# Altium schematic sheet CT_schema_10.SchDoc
size 277 x 170 mm
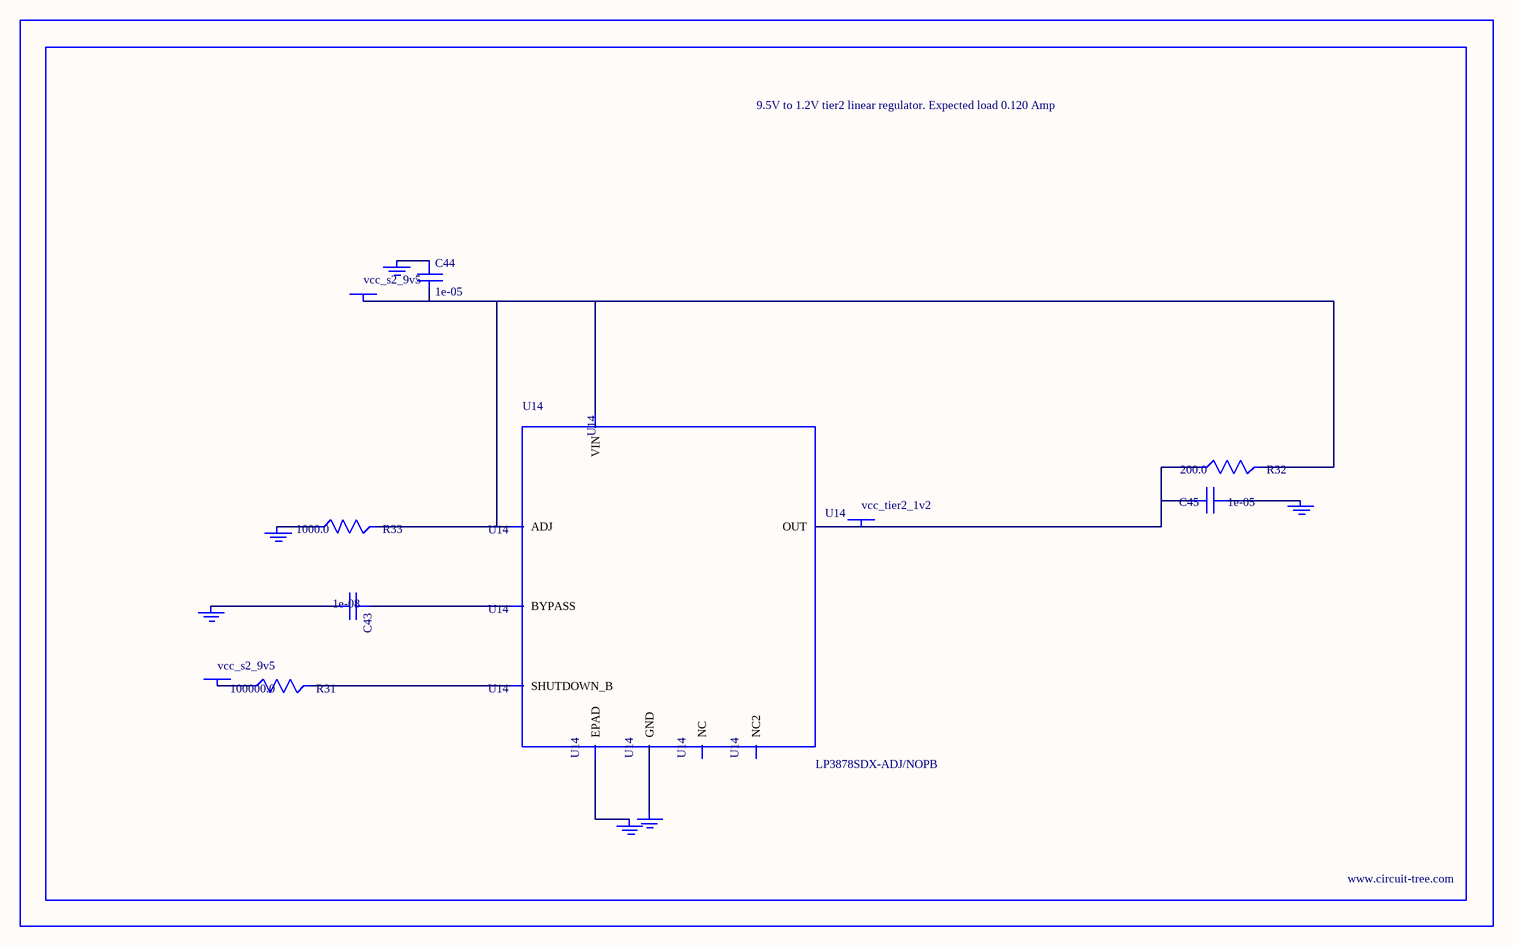
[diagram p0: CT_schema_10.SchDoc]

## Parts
BORDER9  (no value)
C43  1e-08  [C0402]
C44  1e-05  [C1206]
C45  1e-05  [C0805]
GND_INSTANCE_9_0  (no value)
GND_INSTANCE_9_1  (no value)
GND_INSTANCE_9_2  (no value)
GND_INSTANCE_9_3  (no value)
GND_INSTANCE_9_4  (no value)
GND_INSTANCE_9_5  (no value)
POWER_INSTANCE_9_0  vcc_s2_9v5
POWER_INSTANCE_9_1  vcc_s2_9v5
POWER_INSTANCE_9_2  vcc_tier2_1v2
R31  100000.0  [R0603]
R32  200.0  [R0603]
R33  1000.0  [R0603]
U14  LP3878SDX-ADJ/NOPB  [WSON-8]

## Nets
NetC43_1: C43.1 U14.1(BYPASS)
NetC43_2: C43.2 GND_INSTANCE_9_0.0(GND)
NetC44_1: C44.1 GND_INSTANCE_9_1.0(GND)
NetC44_2: C44.2 POWER_INSTANCE_9_0.0(PWR) R32.2 R33.2 U14.4(VIN) U14.6(ADJ)
NetC45_1: C45.1 GND_INSTANCE_9_2.0(GND)
NetC45_2: C45.2 POWER_INSTANCE_9_2.0(PWR) R32.1 U14.5(OUT)
NetGND_INSTANCE_9_3_0: GND_INSTANCE_9_3.0(GND) R33.1
NetGND_INSTANCE_9_4_0: GND_INSTANCE_9_4.0(GND) U14.PAD(EPAD)
NetGND_INSTANCE_9_5_0: GND_INSTANCE_9_5.0(GND) U14.3(GND)
NetPOWER_INSTANCE_9_1_0: POWER_INSTANCE_9_1.0(PWR) R31.1
NetR31_2: R31.2 U14.8(SHUTDOWN_B)

Not connected (* = marked no-connect by the designer): U14 2(NC) 7(NC2)

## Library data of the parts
BORDER9 = BORDER_PAGE9
C43 = C0402C103K3RAC
C44 = C1206C106K3RACTU
C45 = GRM219R60J106ME19D
GND_INSTANCE_9_0-GND_INSTANCE_9_5 = GND
POWER_INSTANCE_9_0-POWER_INSTANCE_9_2 = PWR
R31 = RC0603JR-07100KL
R32 = RC0603JR-07200RL
R33 = RC0603JR-071KL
